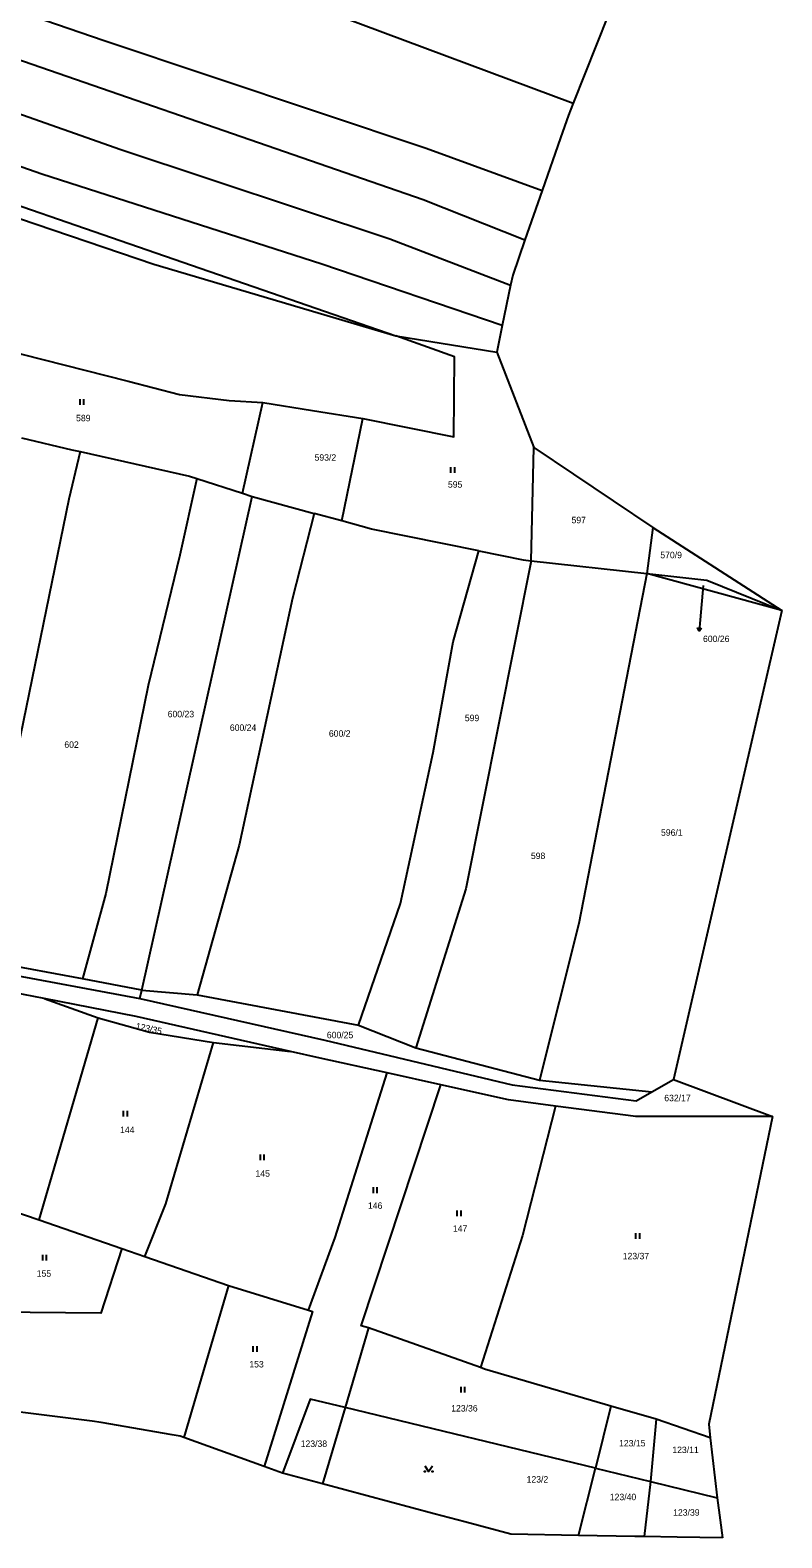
# Model space of a CAD drawing. Extents: x -746176 to -739709, y -1128407 to -1124482.
# Drawn here: x -742205.8 to -742008.1, y -1127528.4 to -1127131.4 of the extents above; entities that cross this region are included whole.
import ezdxf

# ---------------------------------------------------------------- set-up
doc = ezdxf.new("R2010")
doc.units = 0
for name, color, linetype in [('Vrstva 33', 7, 'Continuous'), ('Vrstva 42', 7, 'Continuous'), ('Vrstva 43', 7, 'Continuous'), ('Vrstva 44', 7, 'Continuous')]:
    doc.layers.add(name, color=color, linetype=linetype)

msp = doc.modelspace()

# ---------------------------------------------------------------- linework, layer by layer
at = {"layer": 'Vrstva 33'}
for p, q in [((-742053.72, -1127127.51), (-742062.93, -1127150.64)), ((-742066.27, -1127159.76), (-742071.1, -1127173.63)), ((-742071.1, -1127173.63), (-742075.64, -1127186.64)), ((-742079.42, -1127198.6), (-742081.6, -1127209.14)), ((-742081.6, -1127209.14), (-742083.06, -1127216.18)), ((-742109.57, -1127211.92), (-742083.06, -1127216.18)), ((-742083.06, -1127216.18), (-742073.31, -1127241.28)), ((-742149.95, -1127253.34), (-742144.62, -1127229.42)), ((-742123.8, -1127260.63), (-742118.26, -1127233.67)), ((-742073.98, -1127271.14), (-742073.31, -1127241.28)), ((-742073.31, -1127241.28), (-742042.05, -1127262.32)), ((-742161.94, -1127249.48), (-742149.95, -1127253.34)), ((-742176.39, -1127384.12), (-742147.38, -1127254.17)), ((-742149.95, -1127253.34), (-742147.38, -1127254.17)), ((-742147.38, -1127254.17), (-742131.09, -1127258.63)), ((-742123.8, -1127260.63), (-742131.09, -1127258.63)), ((-742042.05, -1127262.32), (-742043.59, -1127274.46)), ((-742042.05, -1127262.32), (-742008.08, -1127284.25)), ((-742073.98, -1127271.14), (-742043.59, -1127274.46)), ((-742008.08, -1127284.25), (-742043.59, -1127274.46)), ((-742192.07, -1127381.21), (-742222.79, -1127375.51)), ((-742176.39, -1127384.12), (-742192.07, -1127381.21)), ((-742176.91, -1127386.35), (-742176.39, -1127384.12)), ((-742176.39, -1127384.12), (-742161.84, -1127385.41)), ((-742161.84, -1127385.41), (-742119.42, -1127393.4)), ((-742202.09, -1127386.37), (-742187.88, -1127391.48)), ((-742203.39, -1127444.64), (-742187.88, -1127391.48)), ((-742119.42, -1127393.4), (-742104.38, -1127399.34)), ((-742157.54, -1127397.98), (-742137.29, -1127400.3)), ((-742104.38, -1127399.34), (-742071.83, -1127407.9)), ((-742097.77, -1127409.1), (-742111.92, -1127405.97)), ((-742071.83, -1127407.9), (-742042.25, -1127410.93)), ((-742042.25, -1127410.93), (-742036.58, -1127407.72)), ((-742036.58, -1127407.72), (-742010.57, -1127417.44)), ((-742010.57, -1127417.44), (-742027.32, -1127498.39)), ((-742217.73, -1127439.8), (-742203.39, -1127444.64)), ((-742203.39, -1127444.64), (-742181.67, -1127452.16)), ((-742181.67, -1127452.16), (-742175.63, -1127454.26)), ((-742175.63, -1127454.26), (-742153.67, -1127461.89)), ((-742153.67, -1127461.89), (-742165.38, -1127501.9)), ((-742153.67, -1127461.89), (-742132.57, -1127468.42)), ((-742116.77, -1127473.1), (-742122.96, -1127494.02)), ((-742087.32, -1127483.52), (-742116.77, -1127473.1)), ((-742189.51, -1127497.64), (-742238.51, -1127491.51)), ((-742122.96, -1127494.02), (-742128.92, -1127514.16)), ((-742057.12, -1127510.01), (-742122.96, -1127494.02)), ((-742053.04, -1127493.66), (-742057.12, -1127510.01)), ((-742041.17, -1127497.12), (-742053.04, -1127493.66)), ((-742041.17, -1127497.12), (-742042.61, -1127513.54)), ((-742026.89, -1127502.06), (-742041.17, -1127497.12)), ((-742027.32, -1127498.39), (-742026.89, -1127502.06)), ((-742144.27, -1127509.6), (-742165.38, -1127501.9)), ((-742026.89, -1127502.06), (-742025.05, -1127517.8)), ((-742139.43, -1127511.36), (-742144.27, -1127509.6)), ((-742128.92, -1127514.16), (-742139.43, -1127511.36)), ((-742061.59, -1127527.72), (-742057.12, -1127510.01)), ((-742057.12, -1127510.01), (-742042.61, -1127513.54)), ((-742099.57, -1127521.99), (-742128.92, -1127514.16)), ((-742042.61, -1127513.54), (-742044.27, -1127528.03)), ((-742042.61, -1127513.54), (-742025.05, -1127517.8)), ((-742025.05, -1127517.8), (-742024.3, -1127523.72)), ((-742091.44, -1127524.16), (-742099.57, -1127521.99)), ((-742024.3, -1127523.72), (-742023.72, -1127528.35)), ((-742035.6, -1127528.16), (-742044.27, -1127528.03)), ((-742023.72, -1127528.35), (-742035.6, -1127528.16))]:
    msp.add_line(p, q, dxfattribs=at)
for points in [[(-742527.24, -1126986.86), (-742482.52, -1127005.44), (-742410.26, -1127030.86), (-742263.45, -1127080.11), (-742124.08, -1127127.86), (-742062.93, -1127150.64)], [(-742540.51, -1127007.89), (-742508.14, -1127021.79), (-742465.67, -1127038.76), (-742304.51, -1127093.48), (-742186.57, -1127134.04), (-742101.64, -1127162.49), (-742071.1, -1127173.63)], [(-742548.14, -1127019.47), (-742535.36, -1127026.31), (-742485.61, -1127044.66), (-742396.17, -1127075.85), (-742237.29, -1127129.3), (-742102.44, -1127175.98), (-742075.64, -1127186.64)], [(-742556.03, -1127030.18), (-742540.54, -1127037.88), (-742464.14, -1127065.48), (-742257.87, -1127136.04), (-742181.95, -1127162.82), (-742111.16, -1127186.39), (-742079.42, -1127198.6)], [(-742081.6, -1127209.14), (-742129.12, -1127193.01), (-742202.75, -1127169.34), (-742345.7, -1127119.16), (-742474.83, -1127076.87), (-742507.28, -1127063.47), (-742545.28, -1127047.75), (-742563.37, -1127039.11)], [(-742391.64, -1127117.14), (-742294.31, -1127148.02), (-742109.57, -1127211.92)], [(-742391.64, -1127117.14), (-742217.48, -1127178.02), (-742173.31, -1127193), (-742109.57, -1127211.92)], [(-742062.93, -1127150.64), (-742064.2, -1127153.82), (-742066.27, -1127159.76)], [(-742075.64, -1127186.64), (-742078.87, -1127195.92), (-742079.42, -1127198.6)], [(-742229.11, -1127210.34), (-742207.95, -1127216.71), (-742180, -1127223.79), (-742166.56, -1127227.33), (-742153.47, -1127228.89), (-742144.62, -1127229.42)], [(-742118.26, -1127233.67), (-742094.37, -1127238.45), (-742094.19, -1127217.4), (-742109.57, -1127211.92)], [(-742144.62, -1127229.42), (-742131.53, -1127231.54), (-742118.26, -1127233.67)], [(-742208.04, -1127238.77), (-742194.8, -1127241.9), (-742192.66, -1127242.38)], [(-742192.66, -1127242.38), (-742195.66, -1127254.86), (-742215.86, -1127353.44), (-742222.79, -1127375.51)], [(-742192.66, -1127242.38), (-742163.93, -1127248.84), (-742161.94, -1127249.48)], [(-742161.94, -1127249.48), (-742166.42, -1127269.64), (-742174.74, -1127303.95), (-742185.93, -1127358.67), (-742192.07, -1127381.21)], [(-742131.09, -1127258.63), (-742136.83, -1127280.94), (-742150.79, -1127346.02), (-742161.84, -1127385.41)], [(-742087.75, -1127268.53), (-742116.02, -1127262.76), (-742123.8, -1127260.63)], [(-742119.42, -1127393.4), (-742108.38, -1127361.31), (-742099.75, -1127321.56), (-742094.55, -1127292.44), (-742087.75, -1127268.53)], [(-742087.75, -1127268.53), (-742076.13, -1127270.9), (-742073.98, -1127271.14)], [(-742073.98, -1127271.14), (-742091.23, -1127357.45), (-742104.38, -1127399.34)], [(-742043.59, -1127274.46), (-742061.45, -1127366.63), (-742071.83, -1127407.9)], [(-742043.59, -1127274.46), (-742027.79, -1127276.18), (-742008.08, -1127284.25)], [(-742482.5, -1127277.19), (-742478.71, -1127279.87), (-742435.6, -1127297.95), (-742390.76, -1127324.91), (-742338.36, -1127352.64), (-742294.93, -1127366.2), (-742262.34, -1127370.73), (-742214.62, -1127379.37), (-742176.91, -1127386.35)], [(-742008.08, -1127284.25), (-742025.96, -1127361.68), (-742036.58, -1127407.72)], [(-742202.09, -1127386.37), (-742215.77, -1127383.71), (-742217.46, -1127383.38)], [(-742137.29, -1127400.3), (-742177.91, -1127391.06), (-742202.09, -1127386.37)], [(-742176.91, -1127386.35), (-742128.3, -1127397.32), (-742079.03, -1127409.11), (-742046.4, -1127413.28), (-742042.25, -1127410.93)], [(-742187.88, -1127391.48), (-742174.45, -1127395.26), (-742157.54, -1127397.98)], [(-742175.63, -1127454.26), (-742170.07, -1127440.42), (-742157.54, -1127397.98)], [(-742111.92, -1127405.97), (-742129.55, -1127402.06), (-742137.29, -1127400.3)], [(-742132.57, -1127468.42), (-742125.56, -1127449.24), (-742111.92, -1127405.97)], [(-742116.77, -1127473.1), (-742118.71, -1127472.53), (-742097.77, -1127409.1)], [(-742067.59, -1127414.66), (-742079.94, -1127413.05), (-742097.77, -1127409.1)], [(-742067.59, -1127414.66), (-742076.25, -1127448.77), (-742087.32, -1127483.52)], [(-742010.57, -1127417.44), (-742046.51, -1127417.4), (-742067.59, -1127414.66)], [(-742181.67, -1127452.16), (-742187.21, -1127469.19), (-742224.46, -1127468.86)], [(-742132.57, -1127468.42), (-742131.55, -1127468.74), (-742144.27, -1127509.6)], [(-742053.04, -1127493.66), (-742086.26, -1127483.91), (-742087.32, -1127483.52)], [(-742122.96, -1127494.02), (-742132.12, -1127491.8), (-742139.43, -1127511.36)], [(-742168.46, -1127501.19), (-742187.15, -1127497.94), (-742189.51, -1127497.64)], [(-742165.38, -1127501.9), (-742166.32, -1127501.56), (-742168.46, -1127501.19)], [(-742061.59, -1127527.72), (-742079.34, -1127527.39), (-742091.44, -1127524.16)], [(-742044.27, -1127528.03), (-742046.73, -1127527.99), (-742061.59, -1127527.72)]]:
    msp.add_lwpolyline(points, dxfattribs=at)
at = {"layer": 'Vrstva 43'}
for p, q in [((-742028.77, -1127277.65), (-742029.55, -1127286.7)), ((-742029.81, -1127289.69), (-742030.22, -1127288.65)), ((-742029.55, -1127286.7), (-742029.81, -1127289.69)), ((-742029.81, -1127289.69), (-742029.22, -1127288.74))]:
    msp.add_line(p, q, dxfattribs=at)
at = {"layer": 'Vrstva 44'}
for p, q in [((-742192.67, -1127230.08), (-742192.67, -1127228.58)), ((-742191.67, -1127230.08), (-742191.67, -1127228.58)), ((-742095.12, -1127247.97), (-742095.12, -1127246.47)), ((-742094.12, -1127247.97), (-742094.12, -1127246.47)), ((-742181.22, -1127417.4), (-742181.22, -1127415.9)), ((-742180.22, -1127417.4), (-742180.22, -1127415.9)), ((-742145.25, -1127428.96), (-742145.25, -1127427.46)), ((-742144.25, -1127428.96), (-742144.25, -1127427.46)), ((-742115.51, -1127437.57), (-742115.51, -1127436.07)), ((-742114.51, -1127437.57), (-742114.51, -1127436.07)), ((-742093.47, -1127443.7), (-742093.47, -1127442.2)), ((-742092.47, -1127443.7), (-742092.47, -1127442.2)), ((-742046.45, -1127449.6), (-742046.45, -1127448.1)), ((-742045.45, -1127449.6), (-742045.45, -1127448.1)), ((-742202.47, -1127455.31), (-742202.47, -1127453.81)), ((-742201.47, -1127455.31), (-742201.47, -1127453.81)), ((-742147.13, -1127479.36), (-742147.13, -1127477.86)), ((-742146.13, -1127479.36), (-742146.13, -1127477.86)), ((-742092.45, -1127490.09), (-742092.45, -1127488.59)), ((-742091.45, -1127490.09), (-742091.45, -1127488.59))]:
    msp.add_line(p, q, dxfattribs=at)
msp.add_lwpolyline([(-742101.99, -1127509.39), (-742100.99, -1127510.89), (-742099.99, -1127509.39)], dxfattribs=at)
for centre in [(-742101.99, -1127510.89), (-742099.99, -1127510.89)]:
    msp.add_circle(centre, 0.1, dxfattribs=at)

# ---------------------------------------------------------------- texts
at = {"layer": 'Vrstva 42'}
for s, p in [('589', (-742193.72, -1127234.39)), ('593/2', (-742130.99, -1127244.77)), ('595', (-742095.91, -1127251.87)), ('597', (-742063.4, -1127261.24)), ('570/9', (-742040.04, -1127270.45)), ('600/26', (-742028.81, -1127292.52)), ('600/23', (-742169.62, -1127312.32)), ('600/24', (-742153.27, -1127315.9)), ('599', (-742091.46, -1127313.35)), ('600/2', (-742127.22, -1127317.44)), ('602', (-742196.81, -1127320.37)), ('596/1', (-742039.86, -1127343.51)), ('598', (-742074.09, -1127349.64)), ('600/25', (-742127.76, -1127396.82)), ('632/17', (-742039, -1127413.4)), ('144', (-742182.15, -1127421.79)), ('145', (-742146.53, -1127433.27)), ('146', (-742116.95, -1127441.73)), ('147', (-742094.61, -1127447.77)), ('123/37', (-742049.93, -1127455.02)), ('155', (-742204.07, -1127459.61)), ('153', (-742148.15, -1127483.49)), ('123/36', (-742095.05, -1127495.09)), ('123/38', (-742134.64, -1127504.42)), ('123/15', (-742050.9, -1127504.28)), ('123/11', (-742036.88, -1127506.03)), ('123/2', (-742075.21, -1127513.79)), ('123/40', (-742053.33, -1127518.44)), ('123/39', (-742036.67, -1127522.52))]:
    msp.add_text(s, height=1.7, dxfattribs=at).set_placement(p)
msp.add_text('123/35', height=1.7, rotation=348, dxfattribs=at).set_placement((-742178.15, -1127394.39))

doc.saveas('drawing.dxf')
